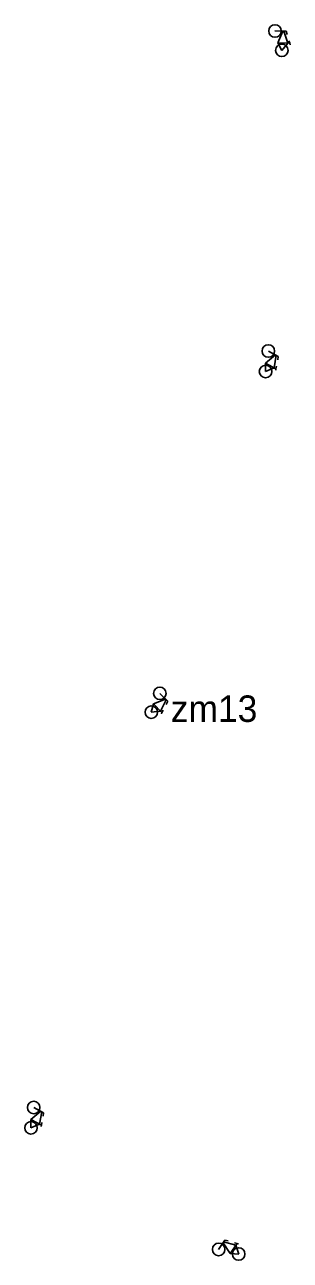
# Model space of a CAD drawing. Extents: x -555070 to -553076, y -1186731 to -1182766.
# Drawn here: x -554441 to -554261, y -1186731 to -1185890 of the extents above; entities that cross this region are included whole.
import ezdxf

# ---------------------------------------------------------------- set-up
doc = ezdxf.new("R2010")
doc.units = 0
doc.layers.add('Level 10', color=7, linetype='Continuous')
doc.layers.add('Level 58', color=7, linetype='Continuous')

msp = doc.modelspace()

# ---------------------------------------------------------------- linework, layer by layer
at = {"layer": 'Level 58'}
for p, q in [((-554271.01, -1185894.73), (-554263.37, -1185894.86)), ((-554269.09, -1185902.89), (-554265.58, -1185894.82)), ((-554264.87, -1185894.83), (-554262.26, -1185903.07)), ((-554263.37, -1185894.86), (-554262.6, -1185897.18)), ((-554260.89, -1185903.12), (-554269.09, -1185902.89)), ((-554269.09, -1185902.89), (-554266.33, -1185907.93)), ((-554266.33, -1185907.93), (-554262.26, -1185903.07)), ((-554260.89, -1185903.12), (-554261.47, -1185901.4)), ((-554260.89, -1185903.12), (-554260.59, -1185904.07)), ((-554277.52, -1186120.52), (-554270.71, -1186114.95)), ((-554275.5, -1186112.39), (-554268.76, -1186115.99)), ((-554270.08, -1186115.28), (-554271.53, -1186123.81)), ((-554268.76, -1186115.99), (-554269.14, -1186118.4)), ((-554270.33, -1186124.47), (-554277.52, -1186120.52)), ((-554277.52, -1186120.52), (-554277.37, -1186126.26)), ((-554277.37, -1186126.26), (-554271.53, -1186123.81)), ((-554270.33, -1186124.47), (-554270.06, -1186122.68)), ((-554270.33, -1186124.47), (-554270.5, -1186125.46)), ((-554353.51, -1186352.36), (-554345.38, -1186348.99)), ((-554349.23, -1186345.16), (-554343.82, -1186350.55)), ((-554344.87, -1186349.49), (-554348.73, -1186357.23)), ((-554343.82, -1186350.55), (-554344.88, -1186352.75)), ((-554353.51, -1186352.36), (-554355.02, -1186357.9)), ((-554355.02, -1186357.9), (-554348.73, -1186357.23)), ((-554347.77, -1186358.22), (-554353.51, -1186352.36)), ((-554347.77, -1186358.22), (-554348.21, -1186359.11)), ((-554347.77, -1186358.22), (-554346.99, -1186356.58)), ((-554434.94, -1186626.72), (-554428.21, -1186630.32)), ((-554436.96, -1186634.85), (-554430.16, -1186629.28)), ((-554429.77, -1186638.81), (-554436.96, -1186634.85)), ((-554436.96, -1186634.85), (-554436.81, -1186640.6)), ((-554429.52, -1186629.61), (-554430.98, -1186638.14)), ((-554428.21, -1186630.32), (-554428.58, -1186632.74)), ((-554436.81, -1186640.6), (-554430.98, -1186638.14)), ((-554429.77, -1186638.81), (-554429.94, -1186639.79)), ((-554429.77, -1186638.81), (-554429.5, -1186637.01)), ((-554309.29, -1186723.27), (-554305.09, -1186716.89)), ((-554301.38, -1186726.03), (-554306.31, -1186718.74)), ((-554305.92, -1186718.14), (-554297.56, -1186720.37)), ((-554305.09, -1186716.89), (-554302.72, -1186717.49)), ((-554296.79, -1186719.23), (-554301.38, -1186726.03)), ((-554296.79, -1186719.23), (-554298.55, -1186718.8)), ((-554295.65, -1186726.41), (-554297.56, -1186720.37)), ((-554296.79, -1186719.23), (-554295.83, -1186719.49)), ((-554301.38, -1186726.03), (-554295.65, -1186726.41))]:
    msp.add_line(p, q, dxfattribs=at)
for centre in [(-554271.01, -1185894.74), (-554266.33, -1185907.92), (-554275.5, -1186112.39), (-554277.37, -1186126.26), (-554349.23, -1186345.16), (-554355.02, -1186357.9), (-554434.94, -1186626.73), (-554436.81, -1186640.59), (-554309.29, -1186723.27), (-554295.65, -1186726.41)]:
    msp.add_circle(centre, 4.25, dxfattribs=at)

# ---------------------------------------------------------------- texts
at = {"layer": 'Level 10'}
msp.add_text('zm13', height=18, dxfattribs=at).set_placement((-554341.81, -1186364.58))

doc.saveas('drawing.dxf')
